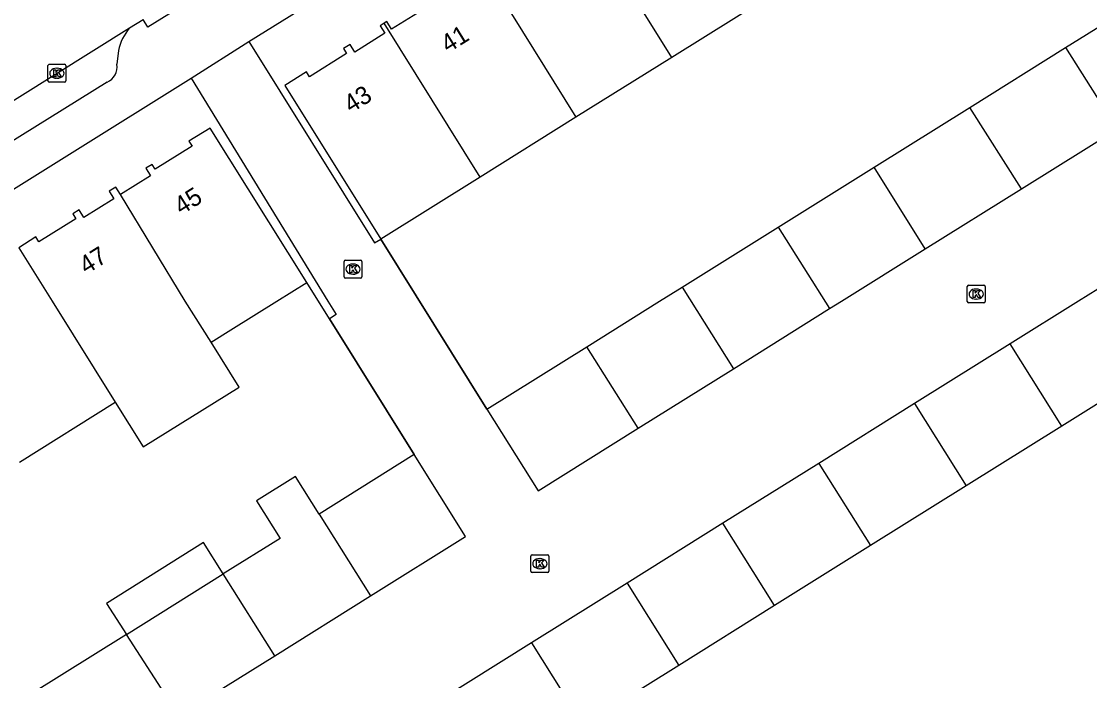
# Model space of a CAD drawing. Extents: x 157767 to 159171, y 387842 to 389425.
# Drawn here: x 158535.7 to 158595.3, y 387978.8 to 388015.6 of the extents above; entities that cross this region are included whole.
import ezdxf

# ---------------------------------------------------------------- set-up
doc = ezdxf.new("R2010")
doc.units = 0
for name, color, linetype in [('IMGEO_Kolk', 7, 'Continuous'), ('IMGEO_Muur', 7, 'Continuous'), ('IMGEO_Pand', 7, 'Continuous'), ('IMGEO_Pand_nummerreeks', 7, 'Continuous'), ('IMGEO_Rijbaan_lokaal_open', 7, 'Continuous'), ('IMGEO_Voetpad_open', 7, 'Continuous')]:
    doc.layers.add(name, color=color, linetype=linetype)

msp = doc.modelspace()

# ---------------------------------------------------------------- linework, layer by layer
at = {"layer": 'IMGEO_Kolk'}
for p, q in [((158537.163, 388012.286), (158537.163, 388013.138)), ((158537.238, 388013.212), (158538.09, 388013.212)), ((158537.651, 388012.992), (158537.676, 388012.992)), ((158538.164, 388013.138), (158538.164, 388012.286)), ((158538.09, 388012.212), (158537.238, 388012.212)), ((158537.674, 388012.432), (158537.649, 388012.432)), ((158553.675, 388001.358), (158553.675, 388002.21)), ((158553.75, 388002.284), (158554.602, 388002.284)), ((158554.163, 388002.064), (158554.188, 388002.064)), ((158554.676, 388002.21), (158554.676, 388001.358)), ((158554.186, 388001.504), (158554.161, 388001.504)), ((158554.602, 388001.284), (158553.75, 388001.284)), ((158588.436, 387999.971), (158588.436, 388000.823)), ((158588.511, 388000.897), (158589.363, 388000.897)), ((158589.437, 388000.823), (158589.437, 387999.971)), ((158588.924, 388000.677), (158588.949, 388000.677)), ((158589.363, 387999.897), (158588.511, 387999.897)), ((158588.947, 388000.117), (158588.922, 388000.117)), ((158564.098, 387984.928), (158564.098, 387985.78)), ((158564.173, 387985.854), (158565.025, 387985.854)), ((158564.586, 387985.634), (158564.611, 387985.634)), ((158565.099, 387985.78), (158565.099, 387984.928)), ((158565.025, 387984.854), (158564.173, 387984.854)), ((158564.609, 387985.074), (158564.584, 387985.074))]:
    msp.add_line(p, q, dxfattribs=at)
for points in [[(158537.163, 388012.286), (158537.163, 388013.138)], [(158537.238, 388013.212), (158538.09, 388013.212)], [(158537.484, 388012.912), (158537.607, 388012.912), (158537.607, 388012.761), (158537.737, 388012.912), (158537.901, 388012.912), (158537.755, 388012.761), (158537.908, 388012.512), (158537.756, 388012.512), (158537.671, 388012.676), (158537.607, 388012.609), (158537.607, 388012.512), (158537.484, 388012.512), (158537.484, 388012.912)], [(158538.164, 388013.138), (158538.164, 388012.286)], [(158538.09, 388012.212), (158537.238, 388012.212)], [(158553.675, 388001.358), (158553.675, 388002.21)], [(158553.75, 388002.284), (158554.602, 388002.284)], [(158553.996, 388001.984), (158554.119, 388001.984), (158554.119, 388001.833), (158554.249, 388001.984), (158554.413, 388001.984), (158554.267, 388001.833), (158554.42, 388001.584), (158554.268, 388001.584), (158554.183, 388001.748), (158554.119, 388001.681), (158554.119, 388001.584), (158553.996, 388001.584), (158553.996, 388001.984)], [(158554.676, 388002.21), (158554.676, 388001.358)], [(158554.602, 388001.284), (158553.75, 388001.284)], [(158588.436, 387999.971), (158588.436, 388000.823)], [(158588.511, 388000.897), (158589.363, 388000.897)], [(158589.437, 388000.823), (158589.437, 387999.971)], [(158588.757, 388000.597), (158588.88, 388000.597), (158588.88, 388000.446), (158589.01, 388000.597), (158589.174, 388000.597), (158589.028, 388000.446), (158589.181, 388000.197), (158589.029, 388000.197), (158588.944, 388000.361), (158588.88, 388000.294), (158588.88, 388000.197), (158588.757, 388000.197), (158588.757, 388000.597)], [(158589.363, 387999.897), (158588.511, 387999.897)], [(158564.098, 387984.928), (158564.098, 387985.78)], [(158564.173, 387985.854), (158565.025, 387985.854)], [(158564.419, 387985.554), (158564.542, 387985.554), (158564.542, 387985.403), (158564.672, 387985.554), (158564.836, 387985.554), (158564.69, 387985.403), (158564.843, 387985.154), (158564.691, 387985.154), (158564.606, 387985.318), (158564.542, 387985.251), (158564.542, 387985.154), (158564.419, 387985.154), (158564.419, 387985.554)], [(158565.099, 387985.78), (158565.099, 387984.928)], [(158565.025, 387984.854), (158564.173, 387984.854)]]:
    msp.add_lwpolyline(points, dxfattribs=at)
for centre, start, end in [((158537.24, 388013.136), 91.55205, 178.44795), ((158537.24, 388013.136), 91.55205, 178.44795), ((158538.088, 388013.136), 1.55205, 88.44795), ((158538.088, 388013.136), 1.55205, 88.44795), ((158537.24, 388012.288), 181.55205, 268.44795), ((158537.24, 388012.288), 181.55205, 268.44795), ((158538.088, 388012.288), 271.55205, 358.44795), ((158538.088, 388012.288), 271.55205, 358.44795), ((158553.752, 388002.208), 91.55205, 178.44795), ((158553.752, 388002.208), 91.55205, 178.44795), ((158554.6, 388002.208), 1.55205, 88.44795), ((158554.6, 388002.208), 1.55205, 88.44795), ((158553.752, 388001.36), 181.55205, 268.44795), ((158553.752, 388001.36), 181.55205, 268.44795), ((158554.6, 388001.36), 271.55205, 358.44795), ((158554.6, 388001.36), 271.55205, 358.44795), ((158588.513, 388000.821), 91.55205, 178.44795), ((158588.513, 388000.821), 91.55205, 178.44795), ((158589.361, 388000.821), 1.55205, 88.44795), ((158589.361, 388000.821), 1.55205, 88.44795), ((158588.513, 387999.973), 181.55205, 268.44795), ((158588.513, 387999.973), 181.55205, 268.44795), ((158589.361, 387999.973), 271.55205, 358.44795), ((158589.361, 387999.973), 271.55205, 358.44795), ((158564.175, 387985.778), 91.55205, 178.44795), ((158564.175, 387985.778), 91.55205, 178.44795), ((158565.023, 387985.778), 1.55205, 88.44795), ((158565.023, 387985.778), 1.55205, 88.44795), ((158564.175, 387984.93), 181.55205, 268.44795), ((158564.175, 387984.93), 181.55205, 268.44795), ((158565.023, 387984.93), 271.55205, 358.44795), ((158565.023, 387984.93), 271.55205, 358.44795)]:
    msp.add_arc(centre, 0.0765, start, end, dxfattribs=at)
for centre, major_axis, ratio, start_param, end_param in [((158537.65, 388012.712), (-0.387, 0.002), 0.722429, 4.712389, 7.853982), ((158537.675, 388012.712), (-0.39, 0.002), 0.717154, 1.570796, 4.712389), ((158554.162, 388001.784), (-0.387, 0.002), 0.722429, 4.712389, 7.853982), ((158554.187, 388001.784), (-0.39, 0.002), 0.717154, 1.570796, 4.712389), ((158588.923, 388000.397), (-0.387, 0.002), 0.722429, 4.712389, 7.853982), ((158588.948, 388000.397), (-0.39, 0.002), 0.717154, 1.570796, 4.712389), ((158564.585, 387985.354), (-0.387, 0.002), 0.722429, 4.712389, 7.853982), ((158564.61, 387985.354), (-0.39, 0.002), 0.717154, 1.570796, 4.712389)]:
    msp.add_ellipse(centre, major_axis=major_axis, ratio=ratio, start_param=start_param, end_param=end_param, dxfattribs=at)
at = {"layer": 'IMGEO_Muur'}
for points in [[(158561.649, 387993.981), (158555.735, 388003.46)], [(158552.862, 387999.02), (158551.599, 388001.043)], [(158557.596, 387991.439), (158552.862, 387999.02)]]:
    msp.add_lwpolyline(points, dxfattribs=at)
at = {"layer": 'IMGEO_Pand'}
for points in [[(158571.95, 388013.598), (158566.608, 388022.19)], [(158561.273, 388018.854), (158560.171, 388018.164), (158560.342, 388017.892), (158558.275, 388016.6), (158558.105, 388016.873), (158557.74, 388016.645), (158558.007, 388016.22), (158556.324, 388015.167), (158556.057, 388015.592), (158555.916, 388015.504)], [(158561.273, 388018.854), (158566.602, 388010.254)], [(158593.922, 388014.141), (158599.282, 388017.488)], [(158577.29, 388016.937), (158571.95, 388013.598)], [(158555.916, 388015.504), (158555.693, 388015.364), (158555.96, 388014.94), (158554.276, 388013.887), (158554.01, 388014.313), (158553.645, 388014.085), (158553.815, 388013.813), (158551.748, 388012.52), (158551.579, 388012.793), (158550.371, 388012.038), (158555.735, 388003.46)], [(158561.261, 388006.915), (158555.916, 388015.504)], [(158588.579, 388010.805), (158593.922, 388014.141)], [(158593.922, 388014.141), (158596.796, 388009.599)], [(158571.95, 388013.598), (158566.602, 388010.254)], [(158583.238, 388007.469), (158588.579, 388010.805)], [(158591.454, 388006.263), (158588.579, 388010.805)], [(158566.602, 388010.254), (158561.261, 388006.915)], [(158546.258, 387997.704), (158547.36, 387998.393), (158549.931, 388000), (158551.599, 388001.043), (158546.213, 388009.657), (158545.028, 388008.916), (158545.198, 388008.646), (158543.143, 388007.359), (158542.973, 388007.631), (158542.619, 388007.409), (158542.884, 388006.987), (158541.21, 388005.94)], [(158591.454, 388006.263), (158596.796, 388009.599)], [(158577.896, 388004.134), (158583.238, 388007.469)], [(158586.097, 388002.918), (158583.238, 388007.469)], [(158561.261, 388006.915), (158555.735, 388003.46)], [(158541.21, 388005.94), (158540.945, 388006.363), (158540.582, 388006.137), (158540.847, 388005.715), (158539.172, 388004.667), (158538.908, 388005.09), (158538.545, 388004.863), (158538.714, 388004.593), (158536.658, 388003.307), (158536.49, 388003.579), (158535.538, 388002.982)], [(158586.097, 388002.918), (158591.454, 388006.263)], [(158546.258, 387997.704), (158544.824, 388000), (158541.21, 388005.94)], [(158572.538, 388000.788), (158577.896, 388004.134)], [(158577.896, 388004.134), (158580.756, 387999.582)], [(158535.538, 388002.982), (158537.399, 388000), (158540.917, 387994.365)], [(158580.756, 387999.582), (158581.424, 388000), (158586.097, 388002.918)], [(158567.213, 387997.459), (158571.276, 388000), (158572.538, 388000.788)], [(158572.538, 388000.788), (158575.395, 387996.231)], [(158599.123, 387996.415), (158596.882, 388000), (158596.25, 388001.011), (158594.633, 388000), (158590.823, 387997.618)], [(158575.395, 387996.231), (158580.756, 387999.582)], [(158540.917, 387994.365), (158542.478, 387991.865), (158547.821, 387995.202), (158546.258, 387997.704)], [(158561.649, 387993.981), (158567.213, 387997.459)], [(158570.077, 387992.906), (158567.213, 387997.459)], [(158590.823, 387997.618), (158585.487, 387994.281)], [(158593.714, 387993.033), (158590.823, 387997.618)], [(158570.077, 387992.906), (158575.395, 387996.231)], [(158599.123, 387996.415), (158593.714, 387993.033)], [(158535.574, 387991.024), (158540.917, 387994.365)], [(158585.487, 387994.281), (158580.158, 387990.95)], [(158585.487, 387994.281), (158588.369, 387989.691)], [(158561.649, 387993.981), (158564.501, 387989.42), (158570.077, 387992.906)], [(158593.714, 387993.033), (158588.369, 387989.691)], [(158557.596, 387991.439), (158552.288, 387988.12)], [(158555.157, 387983.561), (158560.452, 387986.871), (158557.596, 387991.439)], [(158580.158, 387990.95), (158574.81, 387987.606)], [(158580.158, 387990.95), (158583.037, 387986.358)], [(158552.288, 387988.12), (158550.971, 387990.213), (158548.804, 387988.85), (158550.118, 387986.763), (158546.943, 387984.778)], [(158588.369, 387989.691), (158583.037, 387986.358)], [(158552.288, 387988.12), (158555.157, 387983.561)], [(158574.81, 387987.606), (158569.467, 387984.265)], [(158577.689, 387983.014), (158574.81, 387987.606)], [(158546.943, 387984.778), (158545.841, 387986.531), (158540.431, 387983.13), (158541.544, 387981.403)], [(158583.037, 387986.358), (158577.689, 387983.014)], [(158541.544, 387981.403), (158546.943, 387984.778)], [(158549.81, 387980.217), (158546.943, 387984.778)], [(158569.467, 387984.265), (158564.131, 387980.929)], [(158569.467, 387984.265), (158572.341, 387979.67)], [(158549.81, 387980.217), (158555.157, 387983.561)], [(158577.689, 387983.014), (158572.341, 387979.67)], [(158541.544, 387981.403), (158536.208, 387978.066)], [(158544.463, 387976.874), (158541.544, 387981.403)], [(158564.131, 387980.929), (158558.764, 387977.574)], [(158564.131, 387980.929), (158567.009, 387976.336)], [(158544.463, 387976.874), (158549.81, 387980.217)], [(158572.341, 387979.67), (158567.009, 387976.336)]]:
    msp.add_lwpolyline(points, dxfattribs=at)
at = {"layer": 'IMGEO_Rijbaan_lokaal_open'}
for points in [[(158541.713, 388015.24), (158542.469, 388015.712)], [(158519.948, 388001.691), (158531.454, 388008.839), (158541.713, 388015.24)], [(158545.154, 388012.431), (158548.372, 388014.479)], [(158548.372, 388014.479), (158555.38, 388003.25), (158555.735, 388003.46)], [(158545.154, 388012.431), (158552.776, 388000), (158553.236, 387999.25), (158552.862, 387999.02), (158557.596, 387991.439)], [(158555.735, 388003.46), (158561.649, 387993.981)]]:
    msp.add_lwpolyline(points, dxfattribs=at)
at = {"layer": 'IMGEO_Voetpad_open'}
for points in [[(158548.372, 388014.479), (158586.39, 388038.074), (158587.736, 388040.994), (158612.65, 388056.606)], [(158547.157, 388018.626), (158547.418, 388018.2), (158542.73, 388015.286), (158542.469, 388015.712)], [(158541.096, 388013.979), (158541.012, 388013.216)], [(158512.483, 387992.064), (158525.213, 388000), (158545.154, 388012.431)], [(158540.46, 388012.223), (158523.631, 388001.748)]]:
    msp.add_lwpolyline(points, dxfattribs=at)
for centre, radius, start, end in [((158543.832, 388013.422), 2.792, 139.36796, 168.48757), ((158540.105, 388013.07), 0.918, 292.72589, 9.13551)]:
    msp.add_arc(centre, radius, start, end, dxfattribs=at)

# ---------------------------------------------------------------- texts
at = {"layer": 'IMGEO_Pand_nummerreeks'}
for s, rotation, p in [('41', 31.7897, (158559.477, 388013.822)), ('43', 31.7897, (158554.058, 388010.464)), ('45', 32.01575, (158544.602, 388004.782)), ('47', 32.01688, (158539.303, 388001.469))]:
    msp.add_text(s, height=1, rotation=rotation, dxfattribs=at).set_placement(p)

doc.saveas('drawing.dxf')
